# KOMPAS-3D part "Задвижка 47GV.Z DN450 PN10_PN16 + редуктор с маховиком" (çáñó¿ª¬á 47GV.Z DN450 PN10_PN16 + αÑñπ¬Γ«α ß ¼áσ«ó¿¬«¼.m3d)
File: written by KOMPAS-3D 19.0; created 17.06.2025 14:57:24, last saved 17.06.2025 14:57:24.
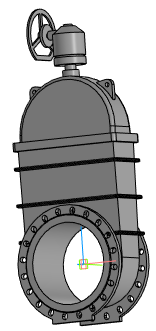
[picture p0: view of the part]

Document properties: Полное имя файла: Задвижка 47GV.Z DN450 PN10_PN16 + редуктор с маховиком.a3d

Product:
- Part/product: Задвижка 47GV.Z DN450 PN10_PN16 + редуктор с маховиком
    Масса: 973.321

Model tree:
1. Операция без истории:1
